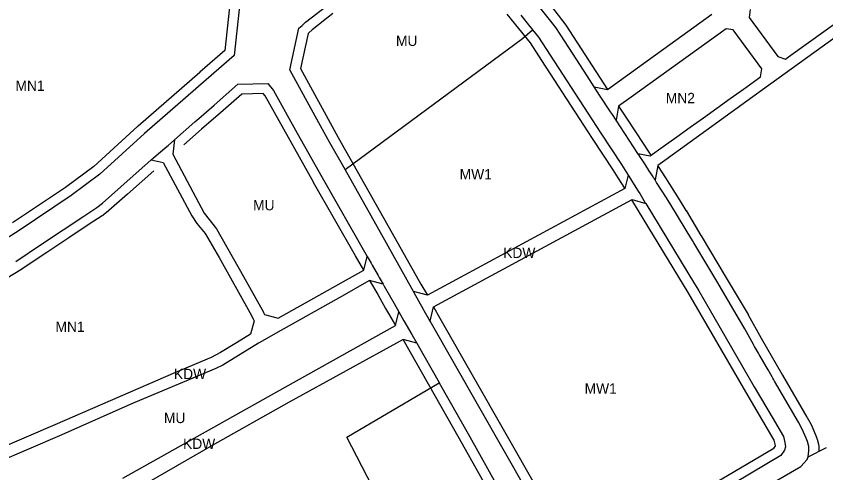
# Model space of a CAD drawing. Extents: x 7435758 to 7439981, y 5550649 to 5554049.
# Drawn here: x 7437442.5 to 7437850.9, y 5551538.4 to 5551768.7 of the extents above; entities that cross this region are included whole.
import ezdxf

# ---------------------------------------------------------------- set-up
doc = ezdxf.new("R2010")
doc.units = 0
for name, color, linetype in [('linie_rozgraniczające', 7, 'Continuous'), ('linie_zabudowy_nieprzekraczalne', 7, 'Continuous'), ('oznaczenia_przeznaczen', 7, 'Continuous')]:
    doc.layers.add(name, color=color, linetype=linetype)

msp = doc.modelspace()

# ---------------------------------------------------------------- linework, layer by layer
at = {"layer": 'linie_rozgraniczające'}
for p, q in [((7437710.94, 5551767.9), (7437702.04, 5551778.99)), ((7437555.16, 5551773.75), (7437552.52, 5551748.9)), ((7437588.51, 5551765.64), (7437599.12, 5551773.94)), ((7437812.75, 5551772.12), (7437812.29, 5551768.05)), ((7437697.09, 5551769.19), (7437701.61, 5551763.54)), ((7437714.81, 5551763.01), (7437710.94, 5551767.9)), ((7437740.84, 5551731.77), (7437793.51, 5551769.78)), ((7437812.29, 5551768.05), (7437826.8, 5551748.37)), ((7437832.18, 5551748.17), (7437860.01, 5551768.18)), ((7437585.14, 5551762.59), (7437586.77, 5551764.06)), ((7437586.77, 5551764.06), (7437588.51, 5551765.64)), ((7437701.61, 5551763.54), (7437702.78, 5551762.08)), ((7437721.23, 5551752.85), (7437714.81, 5551763.01)), ((7437866.87, 5551766.02), (7437819.07, 5551731.54)), ((7437580.6, 5551741.62), (7437585.14, 5551762.59)), ((7437697.86, 5551757.42), (7437703.01, 5551761.8)), ((7437702.78, 5551762.08), (7437702.87, 5551761.97)), ((7437702.87, 5551761.97), (7437702.97, 5551761.85)), ((7437702.97, 5551761.85), (7437703.01, 5551761.8)), ((7437703.01, 5551761.8), (7437705.95, 5551758.13)), ((7437800.68, 5551762.28), (7437752.72, 5551727.88)), ((7437804.12, 5551761.79), (7437800.68, 5551762.28)), ((7437818.64, 5551742.12), (7437804.12, 5551761.79)), ((7437608.38, 5551691.31), (7437697.86, 5551757.42)), ((7437705.95, 5551758.13), (7437711.81, 5551749.05)), ((7437730.46, 5551738.54), (7437721.23, 5551752.85)), ((7437552.52, 5551748.9), (7437538.38, 5551736.61)), ((7437711.81, 5551749.05), (7437730.8, 5551719.8)), ((7437826.8, 5551748.37), (7437830.59, 5551747.03)), ((7437830.59, 5551747.03), (7437832.18, 5551748.17)), ((7437593.36, 5551718.32), (7437580.6, 5551741.62)), ((7437734.09, 5551733.01), (7437730.46, 5551738.54)), ((7437818.07, 5551738.09), (7437818.64, 5551742.12)), ((7437538.38, 5551736.61), (7437527.95, 5551727.51)), ((7437542.31, 5551723.76), (7437554.35, 5551734.39)), ((7437554.35, 5551734.39), (7437569.37, 5551734.74)), ((7437569.37, 5551734.74), (7437572.2, 5551731.27)), ((7437809.48, 5551731.95), (7437818.07, 5551738.09)), ((7437572.2, 5551731.27), (7437584.28, 5551709.68)), ((7437736.81, 5551728.86), (7437734.09, 5551733.01)), ((7437734.09, 5551733.01), (7437740.84, 5551731.77)), ((7437819.07, 5551731.54), (7437769.74, 5551695.94)), ((7437802.72, 5551727.13), (7437809.48, 5551731.95)), ((7437527.95, 5551727.51), (7437507.26, 5551709.46)), ((7437737.1, 5551728.42), (7437736.81, 5551728.86)), ((7437742.35, 5551720.44), (7437737.1, 5551728.42)), ((7437752.72, 5551727.88), (7437746.4, 5551723.35)), ((7437795.96, 5551722.3), (7437802.72, 5551727.13)), ((7437534.68, 5551717.16), (7437542.31, 5551723.76)), ((7437746.4, 5551723.35), (7437745.15, 5551716.18)), ((7437789.21, 5551717.48), (7437795.96, 5551722.3)), ((7437600.61, 5551705.08), (7437593.36, 5551718.32)), ((7437730.8, 5551719.8), (7437737.41, 5551709.74)), ((7437743.24, 5551719.08), (7437742.35, 5551720.44)), ((7437745.15, 5551716.18), (7437743.24, 5551719.08)), ((7437522.25, 5551706.32), (7437532.65, 5551715.4)), ((7437532.65, 5551715.4), (7437534.68, 5551717.16)), ((7437756.16, 5551699.44), (7437745.15, 5551716.18)), ((7437782.46, 5551712.64), (7437789.21, 5551717.48)), ((7437775.71, 5551707.81), (7437782.46, 5551712.64)), ((7437507.26, 5551709.46), (7437484.74, 5551689.01)), ((7437519.07, 5551703.54), (7437522.25, 5551706.32)), ((7437522.25, 5551706.32), (7437521.46, 5551699.07)), ((7437584.28, 5551709.68), (7437596.77, 5551687.35)), ((7437737.41, 5551709.74), (7437747.86, 5551693.88)), ((7437768.96, 5551702.97), (7437775.71, 5551707.81)), ((7437514.23, 5551699.39), (7437518.5, 5551703.04)), ((7437518.5, 5551703.04), (7437519.07, 5551703.54)), ((7437608.38, 5551691.31), (7437600.61, 5551705.08)), ((7437762.38, 5551698.26), (7437768.96, 5551702.97)), ((7437511.81, 5551697.32), (7437514.23, 5551699.39)), ((7437521.46, 5551699.07), (7437537.32, 5551669.37)), ((7437756.5, 5551698.93), (7437756.16, 5551699.44)), ((7437756.16, 5551699.44), (7437762.38, 5551698.26)), ((7437757.1, 5551698.02), (7437756.5, 5551698.93)), ((7437757.13, 5551697.98), (7437757.1, 5551698.02)), ((7437758.92, 5551695.26), (7437757.13, 5551697.98)), ((7437495.3, 5551682.7), (7437510.51, 5551696.17)), ((7437510.51, 5551696.17), (7437511.81, 5551697.32)), ((7437510.51, 5551696.17), (7437516.65, 5551694.89)), ((7437516.65, 5551694.89), (7437531.04, 5551668.06)), ((7437747.86, 5551693.88), (7437751.24, 5551688.54)), ((7437759.61, 5551694.2), (7437758.92, 5551695.26)), ((7437762.07, 5551690.41), (7437759.61, 5551694.2)), ((7437769.74, 5551695.94), (7437766.13, 5551693.34)), ((7437629.36, 5551654.17), (7437608.38, 5551691.31)), ((7437762.19, 5551690.22), (7437762.07, 5551690.41)), ((7437763.48, 5551688.17), (7437762.19, 5551690.22)), ((7437766.13, 5551693.34), (7437764.77, 5551686.13)), ((7437484.74, 5551689.01), (7437470.2, 5551678.27)), ((7437596.77, 5551687.35), (7437618.93, 5551648.65)), ((7437751.24, 5551688.54), (7437749.48, 5551681.86)), ((7437751.24, 5551688.54), (7437751.6, 5551687.96)), ((7437751.6, 5551687.96), (7437752.96, 5551685.82)), ((7437752.96, 5551685.82), (7437754.29, 5551683.71)), ((7437764.25, 5551686.95), (7437763.48, 5551688.17)), ((7437764.46, 5551686.62), (7437764.25, 5551686.95)), ((7437764.77, 5551686.13), (7437764.46, 5551686.62)), ((7437765.6, 5551684.81), (7437764.77, 5551686.13)), ((7437485.95, 5551674.45), (7437495.3, 5551682.7)), ((7437749.48, 5551681.86), (7437650.01, 5551628.04)), ((7437754.29, 5551683.71), (7437754.3, 5551683.71)), ((7437754.3, 5551683.71), (7437756.33, 5551680.37)), ((7437770.51, 5551677.02), (7437765.6, 5551684.81)), ((7437470.2, 5551678.27), (7437443.4, 5551660.3)), ((7437756.33, 5551680.37), (7437757.05, 5551679.19)), ((7437757.05, 5551679.19), (7437759.81, 5551674.64)), ((7437483.17, 5551672.24), (7437485.95, 5551674.45)), ((7437653.08, 5551622.16), (7437753.28, 5551676.25)), ((7437753.28, 5551676.25), (7437760.06, 5551674.24)), ((7437759.81, 5551674.64), (7437760.06, 5551674.24)), ((7437760.06, 5551674.24), (7437784.75, 5551633.67)), ((7437772.72, 5551673.52), (7437770.51, 5551677.02)), ((7437776.12, 5551668.07), (7437772.72, 5551673.52)), ((7437476.57, 5551667.91), (7437483.17, 5551672.24)), ((7437537.32, 5551669.37), (7437543.45, 5551661.43)), ((7437466.18, 5551661.02), (7437476.57, 5551667.91)), ((7437531.04, 5551668.06), (7437533.57, 5551664.2)), ((7437780.98, 5551659.98), (7437776.12, 5551668.07)), ((7437455.22, 5551653.73), (7437466.18, 5551661.02)), ((7437533.57, 5551664.2), (7437537.74, 5551659.09)), ((7437543.45, 5551661.43), (7437557.1, 5551637.43)), ((7437443.4, 5551660.3), (7437422.12, 5551647)), ((7437537.74, 5551659.09), (7437544.83, 5551646.97)), ((7437783.62, 5551655.58), (7437780.98, 5551659.98)), ((7437442.25, 5551645.05), (7437455.22, 5551653.73)), ((7437642.86, 5551629.92), (7437629.36, 5551654.17)), ((7437783.61, 5551655.56), (7437783.62, 5551655.58)), ((7437784.29, 5551654.45), (7437783.61, 5551655.56)), ((7437795.92, 5551634.99), (7437784.29, 5551654.45)), ((7437618.93, 5551648.65), (7437619.59, 5551647.49)), ((7437544.83, 5551646.97), (7437560.31, 5551619.28)), ((7437617.81, 5551640.65), (7437619.59, 5551647.49)), ((7437619.59, 5551647.49), (7437621.5, 5551644.17)), ((7437613.33, 5551638.1), (7437617.81, 5551640.65)), ((7437621.5, 5551644.17), (7437622.11, 5551643.1)), ((7437622.11, 5551643.1), (7437625.09, 5551637.89)), ((7437557.1, 5551637.43), (7437567.16, 5551619.38)), ((7437574.65, 5551616.33), (7437613.33, 5551638.1)), ((7437625.09, 5551637.89), (7437625.65, 5551636.91)), ((7437625.65, 5551636.91), (7437627.56, 5551633.58)), ((7437618.01, 5551633.86), (7437608.04, 5551628.18)), ((7437620.74, 5551635.41), (7437618.01, 5551633.86)), ((7437627.56, 5551633.58), (7437620.74, 5551635.41)), ((7437627.56, 5551633.58), (7437628.17, 5551632.51)), ((7437628.17, 5551632.51), (7437633.2, 5551623.74)), ((7437784.75, 5551633.67), (7437785.86, 5551631.84)), ((7437807.38, 5551615.63), (7437795.92, 5551634.99)), ((7437608.04, 5551628.18), (7437573.23, 5551608.58)), ((7437643.23, 5551629.25), (7437642.86, 5551629.92)), ((7437650.01, 5551628.04), (7437642.86, 5551629.92)), ((7437645.57, 5551625.05), (7437643.23, 5551629.25)), ((7437785.86, 5551631.84), (7437786.82, 5551630.18)), ((7437786.82, 5551630.18), (7437789.4, 5551625.73)), ((7437647.97, 5551620.75), (7437645.57, 5551625.05)), ((7437789.4, 5551625.73), (7437791.88, 5551621.44)), ((7437633.2, 5551623.74), (7437635.6, 5551619.51)), ((7437648.35, 5551620.09), (7437647.97, 5551620.75)), ((7437650.87, 5551615.67), (7437648.35, 5551620.09)), ((7437651.34, 5551614.85), (7437653.08, 5551622.16)), ((7437791.88, 5551621.44), (7437814.86, 5551581.73)), ((7437560.31, 5551619.28), (7437562.05, 5551616.05)), ((7437562.05, 5551616.05), (7437562.56, 5551615.13)), ((7437567.16, 5551619.38), (7437567.22, 5551619.26)), ((7437567.22, 5551619.26), (7437567.79, 5551618.25)), ((7437567.79, 5551618.25), (7437574.65, 5551616.33)), ((7437633.83, 5551612.74), (7437635.6, 5551619.51)), ((7437635.6, 5551619.51), (7437638.09, 5551615.13)), ((7437562.56, 5551615.13), (7437560.61, 5551608.31)), ((7437578.11, 5551581.52), (7437633.83, 5551612.74)), ((7437638.09, 5551615.13), (7437642.09, 5551608.09)), ((7437651.34, 5551614.85), (7437650.87, 5551615.67)), ((7437701.57, 5551526.92), (7437651.34, 5551614.85)), ((7437810.02, 5551611.01), (7437807.38, 5551615.63)), ((7437560.61, 5551608.31), (7437553.64, 5551604.01)), ((7437573.23, 5551608.58), (7437567.77, 5551605.51)), ((7437642.09, 5551608.09), (7437644.58, 5551603.71)), ((7437814.48, 5551603.18), (7437810.02, 5551611.01)), ((7437553.64, 5551604.01), (7437545.49, 5551599)), ((7437564.75, 5551603.81), (7437546.77, 5551592.74)), ((7437567.77, 5551605.51), (7437564.75, 5551603.81)), ((7437637.67, 5551605.66), (7437580.13, 5551574.08)), ((7437644.58, 5551603.71), (7437637.67, 5551605.66)), ((7437644.58, 5551603.71), (7437655.83, 5551583.9)), ((7437815.05, 5551602.18), (7437814.48, 5551603.18)), ((7437816.99, 5551598.76), (7437815.05, 5551602.18)), ((7437540.86, 5551596.51), (7437522.88, 5551589.02)), ((7437545.49, 5551599), (7437540.86, 5551596.51)), ((7437817.4, 5551598.05), (7437816.99, 5551598.76)), ((7437821.35, 5551591.11), (7437817.4, 5551598.05)), ((7437546.77, 5551592.74), (7437543.25, 5551591.01)), ((7437522.88, 5551589.02), (7437461.88, 5551562.63)), ((7437543.25, 5551591.01), (7437531.66, 5551586.18)), ((7437821.79, 5551590.35), (7437821.35, 5551591.11)), ((7437823.82, 5551586.78), (7437821.79, 5551590.35)), ((7437531.66, 5551586.18), (7437501.44, 5551573.48)), ((7437609.34, 5551556.45), (7437655.88, 5551583.82)), ((7437655.83, 5551583.9), (7437655.88, 5551583.82)), ((7437655.88, 5551583.82), (7437670.53, 5551558.04)), ((7437824.19, 5551586.13), (7437823.82, 5551586.78)), ((7437824.23, 5551586.06), (7437824.19, 5551586.13)), ((7437824.69, 5551585.25), (7437824.23, 5551586.06)), ((7437825.1, 5551584.56), (7437824.69, 5551585.25)), ((7437837.12, 5551563.97), (7437825.1, 5551584.56)), ((7437496.28, 5551535.7), (7437578.11, 5551581.52)), ((7437814.86, 5551581.73), (7437823.8, 5551566.5)), ((7437501.44, 5551573.48), (7437464.28, 5551557.13)), ((7437580.13, 5551574.08), (7437541.41, 5551552.18)), ((7437823.8, 5551566.5), (7437829.53, 5551556.73)), ((7437839.09, 5551560.33), (7437837.12, 5551563.97)), ((7437461.88, 5551562.63), (7437430.21, 5551548.94)), ((7437841.1, 5551555.87), (7437839.09, 5551560.33)), ((7437464.28, 5551557.13), (7437427.1, 5551541.11)), ((7437622, 5551531.63), (7437609.34, 5551556.45)), ((7437670.53, 5551558.04), (7437695.96, 5551512.69)), ((7437829.53, 5551556.73), (7437830.32, 5551553.69)), ((7437841.72, 5551554.12), (7437841.1, 5551555.87)), ((7437541.41, 5551552.18), (7437485.75, 5551520.23)), ((7437830.55, 5551551.56), (7437830.11, 5551549.81)), ((7437830.32, 5551553.69), (7437830.55, 5551551.56)), ((7437842.38, 5551551.59), (7437841.72, 5551554.12)), ((7437842.06, 5551546.41), (7437851.26, 5551551.21)), ((7437842.43, 5551549.43), (7437842.38, 5551551.59)), ((7437828.25, 5551547.15), (7437787.93, 5551523.28)), ((7437830.11, 5551549.81), (7437828.25, 5551547.15)), ((7437842.06, 5551546.41), (7437842.43, 5551549.43)), ((7437838.31, 5551541.54), (7437841.6, 5551545.1)), ((7437841.6, 5551545.1), (7437841.75, 5551545.54)), ((7437841.75, 5551545.54), (7437842.06, 5551546.41)), ((7437799.93, 5551519.4), (7437838.31, 5551541.54))]:
    msp.add_line(p, q, dxfattribs=at)
at = {"layer": 'linie_zabudowy_nieprzekraczalne'}
for points in [[(7437726.51, 5551872.44), (7437721.02, 5551868.21), (7437717.65, 5551865.51), (7437705.36, 5551855.64), (7437685.08, 5551838.86), (7437678.17, 5551832.88), (7437678.1, 5551832.82), (7437673.44, 5551828.94), (7437671.49, 5551827.37), (7437676.61, 5551820.64), (7437719.71, 5551764.14), (7437740.84, 5551731.77)], [(7437550.07, 5551773.18), (7437547.75, 5551751.39), (7437535.1, 5551740.38), (7437535.1, 5551740.37), (7437503.97, 5551713.23), (7437503.9, 5551713.16), (7437481.57, 5551692.88), (7437467.33, 5551682.35), (7437440.68, 5551664.5)], [(7437602.2, 5551770), (7437591.73, 5551761.81), (7437590.12, 5551760.35), (7437589.69, 5551759.96), (7437585.88, 5551742.38), (7437604.97, 5551707.51), (7437633.71, 5551656.63), (7437633.73, 5551656.6), (7437646.55, 5551633.57), (7437650.01, 5551628.04)], [(7437749.53, 5551681.89), (7437746.21, 5551687.13), (7437743.66, 5551691.16), (7437733.24, 5551706.99), (7437733.23, 5551706.99), (7437726.62, 5551717.06), (7437726.61, 5551717.08), (7437707.61, 5551746.33), (7437707.6, 5551746.34), (7437701.89, 5551755.2), (7437690.25, 5551769.72)], [(7437617.81, 5551640.65), (7437613.59, 5551647.91), (7437592.43, 5551684.87), (7437592.4, 5551684.91), (7437568.05, 5551728.45), (7437567.04, 5551729.68), (7437556.29, 5551729.44), (7437545.62, 5551720.02), (7437545.58, 5551719.98), (7437535.93, 5551711.63), (7437527.01, 5551703.84)], [(7437746.4, 5551723.35), (7437750.42, 5551717.27), (7437759.18, 5551703.96), (7437760.68, 5551701.68), (7437762.74, 5551698.55)], [(7437511.95, 5551690.76), (7437498.62, 5551678.95), (7437498.61, 5551678.95), (7437489.26, 5551670.7), (7437489.15, 5551670.61), (7437489.07, 5551670.54), (7437486.29, 5551668.33), (7437486.12, 5551668.2), (7437485.91, 5551668.05), (7437479.32, 5551663.74), (7437468.95, 5551656.86), (7437457.99, 5551649.56), (7437445.03, 5551640.9), (7437444.92, 5551640.83), (7437444.85, 5551640.78), (7437437.96, 5551636.59)], [(7437766.13, 5551693.34), (7437766.39, 5551692.94), (7437766.41, 5551692.9), (7437766.42, 5551692.89), (7437770.05, 5551687.13), (7437776.95, 5551676.18), (7437776.96, 5551676.17), (7437780.36, 5551670.72), (7437780.41, 5551670.64), (7437787.9, 5551658.15), (7437788.01, 5551657.97), (7437788.06, 5551657.88), (7437788.56, 5551657.05), (7437788.58, 5551657.01), (7437800.21, 5551637.56), (7437800.22, 5551637.54), (7437811.69, 5551618.17), (7437811.73, 5551618.1), (7437818.39, 5551606.38), (7437829.11, 5551587.61), (7437841.44, 5551566.49), (7437841.51, 5551566.36), (7437841.51, 5551566.35), (7437843.49, 5551562.72), (7437843.63, 5551562.43), (7437843.66, 5551562.38), (7437845.66, 5551557.91), (7437845.76, 5551557.66), (7437845.8, 5551557.55), (7437846.43, 5551555.81), (7437846.49, 5551555.61), (7437846.56, 5551555.39), (7437847.22, 5551552.86), (7437847.24, 5551552.76), (7437847.31, 5551552.44), (7437847.36, 5551552.12), (7437847.38, 5551551.79), (7437847.38, 5551551.69), (7437847.43, 5551549.41)], [(7437653.08, 5551622.16), (7437656.22, 5551616.38), (7437705.89, 5551529.43), (7437723.44, 5551499.81), (7437733, 5551497.15), (7437785.39, 5551527.59), (7437824.77, 5551550.9), (7437825.49, 5551551.92), (7437825.39, 5551552.78), (7437824.87, 5551554.79), (7437810.55, 5551579.2), (7437810.53, 5551579.23), (7437781.56, 5551629.29), (7437756.5, 5551670.46), (7437753.06, 5551676.12)], [(7437620.74, 5551635.41), (7437624.84, 5551628.27), (7437628.86, 5551621.26), (7437630.25, 5551618.8), (7437633.83, 5551612.74)], [(7437708.02, 5551482.1), (7437704.5, 5551488.27), (7437691.65, 5551510.16), (7437691.6, 5551510.25), (7437666.17, 5551555.59), (7437641.24, 5551599.46), (7437637.67, 5551605.66)]]:
    msp.add_lwpolyline(points, dxfattribs=at)

# ---------------------------------------------------------------- texts
at = {"layer": 'oznaczenia_przeznaczen'}
for s, p in [('MU', (7437634.09, 5551753.68)), ('MN1', (7437442.1, 5551731.03)), ('MN2', (7437770.22, 5551724.82)), ('MW1', (7437666.22, 5551686.36)), ('MU', (7437561.99, 5551670.78)), ('KDW', (7437688.18, 5551646.75)), ('MN1', (7437462.3, 5551609.47)), ('KDW', (7437522.05, 5551585.65)), ('MW1', (7437729.26, 5551578.32)), ('MU', (7437517.02, 5551563.48)), ('KDW', (7437526.66, 5551550.44))]:
    msp.add_text(s, height=5.2, dxfattribs=at).set_placement(p)

doc.saveas('drawing.dxf')
